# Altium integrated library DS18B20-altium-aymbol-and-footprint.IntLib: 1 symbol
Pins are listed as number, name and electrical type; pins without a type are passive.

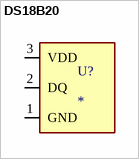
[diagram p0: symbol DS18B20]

## DS18B20
designator U?
Temperature Sensor Digital, Local -55Â°C ~ 125Â°C 9 b, 10 b, 11 b, 12 b TO-92; MF: UMW; MP: DS18B20
footprint TO-92-AMMO
pins: 1 GND (power), 2 DQ (io), 3 VDD (power)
